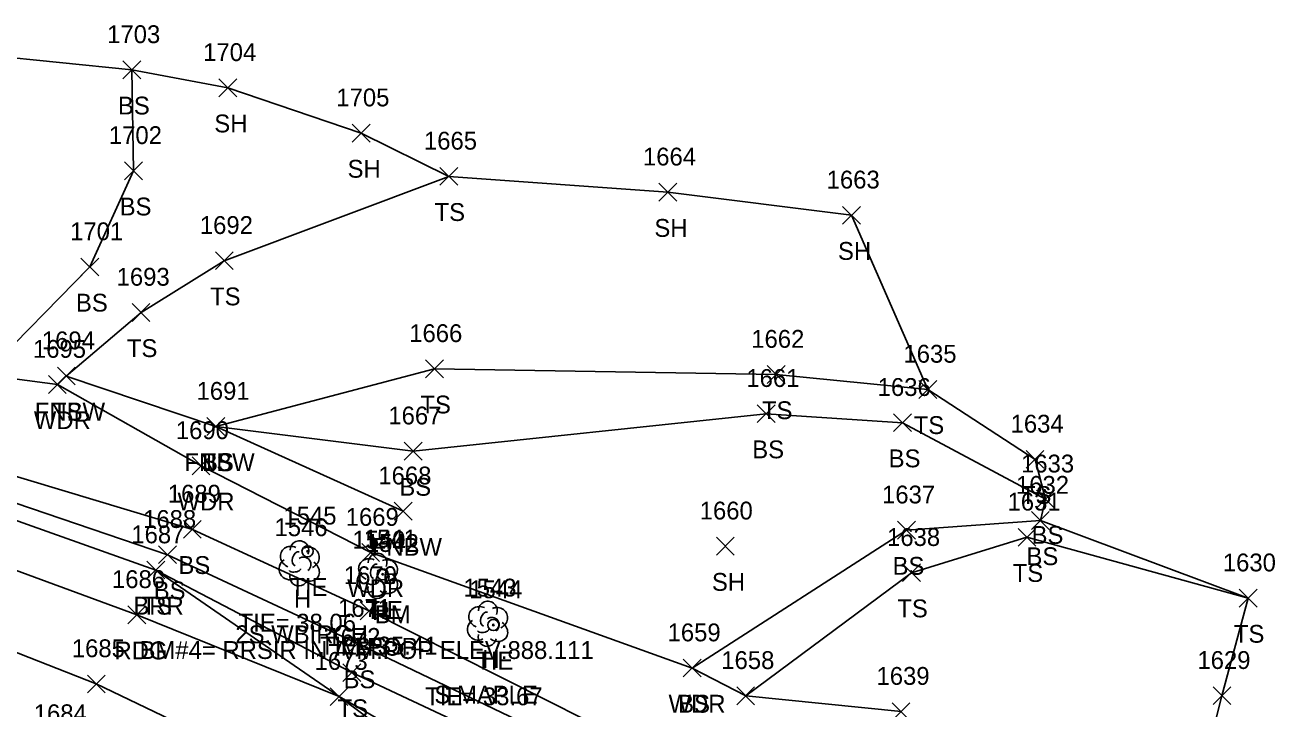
# Model space of a CAD drawing. Extents: x 1600281 to 1602254, y 862855 to 863227.
# Drawn here: x 1602113.6 to 1602253.7, y 863101.9 to 863178.4 of the extents above; entities that cross this region are included whole.
import ezdxf

# ---------------------------------------------------------------- set-up
doc = ezdxf.new("R2010")
doc.units = 0
for name, color, linetype in [('C_A', 7, 'Continuous'), ('C_C', 7, 'Continuous'), ('C_I', 7, 'Continuous'), ('CBP', 7, 'Continuous'), ('CPBM', 7, 'Continuous'), ('L_A', 7, 'Continuous'), ('L_C', 7, 'Continuous'), ('L_I', 7, 'Continuous'), ('L_TIC', 7, 'Continuous'), ('LABL', 7, 'Continuous'), ('LAWA', 7, 'Continuous'), ('LELB', 7, 'Continuous'), ('LFNC', 7, 'Continuous'), ('LSOGP', 7, 'Continuous'), ('LTD', 7, 'Continuous'), ('P_A', 7, 'Continuous'), ('P_I', 7, 'Continuous'), ('P_TIC', 7, 'Continuous'), ('PEU', 7, 'Continuous'), ('PRC', 7, 'Continuous')]:
    doc.layers.add(name, color=color, linetype=linetype)

msp = doc.modelspace()

# ---------------------------------------------------------------- linework, layer by layer
at = {"layer": 'CBP'}
for centre, radius in [((1602145.23, 863119.42), 0.625), ((1602145.23, 863119.42), 0.0833), ((1602153.66, 863116.85), 0.625), ((1602153.66, 863116.85), 0.0833), ((1602166.06, 863111.16), 0.625), ((1602166.06, 863111.16), 0.0833)]:
    msp.add_circle(centre, radius, dxfattribs=at)
at = {"layer": 'CPBM'}
for p, q in [((1602153.95, 863115.85), (1602153.95, 863116.85)), ((1602153.95, 863116.85), (1602154.95, 863116.85)), ((1602154.95, 863115.85), (1602153.95, 863115.85)), ((1602154.45, 863116.35), (1602154.45, 863116.35)), ((1602154.45, 863116.35), (1602154.45, 863116.35)), ((1602154.95, 863116.85), (1602154.95, 863115.85))]:
    msp.add_line(p, q, dxfattribs=at)
at = {"layer": 'L_TIC'}
for points in [[(1602124.54, 863172.4), (1602126.54, 863174.4)], [(1602126.54, 863172.4), (1602124.54, 863174.4)], [(1602135.3, 863170.39), (1602137.3, 863172.39)], [(1602137.3, 863170.39), (1602135.3, 863172.39)], [(1602150.24, 863165.31), (1602152.24, 863167.31)], [(1602152.24, 863165.31), (1602150.24, 863167.31)], [(1602124.73, 863161.08), (1602126.73, 863163.08)], [(1602126.73, 863161.08), (1602124.73, 863163.08)], [(1602160.07, 863160.46), (1602162.07, 863162.46)], [(1602162.07, 863160.46), (1602160.07, 863162.46)], [(1602184.62, 863158.68), (1602186.62, 863160.68)], [(1602186.62, 863158.68), (1602184.62, 863160.68)], [(1602205.21, 863156.1), (1602207.21, 863158.1)], [(1602207.21, 863156.1), (1602205.21, 863158.1)], [(1602119.83, 863150.3), (1602121.83, 863152.3)], [(1602121.83, 863150.3), (1602119.83, 863152.3)], [(1602134.9, 863151), (1602136.9, 863153)], [(1602136.9, 863151), (1602134.9, 863153)], [(1602125.57, 863145.2), (1602127.57, 863147.2)], [(1602127.57, 863145.2), (1602125.57, 863147.2)], [(1602158.47, 863138.88), (1602160.47, 863140.88)], [(1602160.47, 863138.88), (1602158.47, 863140.88)], [(1602117.19, 863138.07), (1602119.19, 863140.07)], [(1602119.19, 863138.07), (1602117.19, 863140.07)], [(1602117.19, 863138.07), (1602119.19, 863140.07)], [(1602119.19, 863138.07), (1602117.19, 863140.07)], [(1602196.76, 863138.24), (1602198.76, 863140.24)], [(1602198.76, 863138.24), (1602196.76, 863140.24)], [(1602116.19, 863137.12), (1602118.19, 863139.12)], [(1602118.19, 863137.12), (1602116.19, 863139.12)], [(1602213.77, 863136.57), (1602215.77, 863138.57)], [(1602215.77, 863136.57), (1602213.77, 863138.57)], [(1602195.64, 863133.85), (1602197.64, 863135.85)], [(1602197.64, 863133.85), (1602195.64, 863135.85)], [(1602133.96, 863132.41), (1602135.96, 863134.41)], [(1602135.96, 863132.41), (1602133.96, 863134.41)], [(1602133.96, 863132.41), (1602135.96, 863134.41)], [(1602135.96, 863132.41), (1602133.96, 863134.41)], [(1602133.96, 863132.41), (1602135.96, 863134.41)], [(1602135.96, 863132.41), (1602133.96, 863134.41)], [(1602210.93, 863132.84), (1602212.93, 863134.84)], [(1602212.93, 863132.84), (1602210.93, 863134.84)], [(1602156.07, 863129.65), (1602158.07, 863131.65)], [(1602158.07, 863129.65), (1602156.07, 863131.65)], [(1602132.29, 863128), (1602134.29, 863130)], [(1602134.29, 863128), (1602132.29, 863130)], [(1602225.78, 863128.73), (1602227.78, 863130.73)], [(1602227.78, 863128.73), (1602225.78, 863130.73)], [(1602226.95, 863124.26), (1602228.95, 863126.26)], [(1602228.95, 863124.26), (1602226.95, 863126.26)], [(1602154.96, 863122.92), (1602156.96, 863124.92)], [(1602156.96, 863122.92), (1602154.96, 863124.92)], [(1602131.32, 863120.88), (1602133.32, 863122.88)], [(1602133.32, 863120.88), (1602131.32, 863122.88)], [(1602211.37, 863120.79), (1602213.37, 863122.79)], [(1602213.37, 863120.79), (1602211.37, 863122.79)], [(1602226.38, 863121.87), (1602228.38, 863123.87)], [(1602228.38, 863121.87), (1602226.38, 863123.87)], [(1602224.87, 863119.99), (1602226.87, 863121.99)], [(1602226.87, 863119.99), (1602224.87, 863121.99)], [(1602128.54, 863118.04), (1602130.54, 863120.04)], [(1602130.54, 863118.04), (1602128.54, 863120.04)], [(1602151.31, 863118.28), (1602153.31, 863120.28)], [(1602153.31, 863118.28), (1602151.31, 863120.28)], [(1602191.07, 863118.99), (1602193.07, 863120.99)], [(1602193.07, 863118.99), (1602191.07, 863120.99)], [(1602127.22, 863116.32), (1602129.22, 863118.32)], [(1602129.22, 863116.32), (1602127.22, 863118.32)], [(1602127.22, 863116.32), (1602129.22, 863118.32)], [(1602129.22, 863116.32), (1602127.22, 863118.32)], [(1602211.93, 863116.02), (1602213.93, 863118.02)], [(1602213.93, 863116.02), (1602211.93, 863118.02)], [(1602249.66, 863113.17), (1602251.66, 863115.17)], [(1602251.66, 863113.17), (1602249.66, 863115.17)], [(1602151.13, 863111.74), (1602153.13, 863113.74)], [(1602153.13, 863111.74), (1602151.13, 863113.74)], [(1602149.82, 863108.07), (1602151.82, 863110.07)], [(1602151.82, 863108.07), (1602149.82, 863110.07)], [(1602187.34, 863105.33), (1602189.34, 863107.33)], [(1602189.34, 863105.33), (1602187.34, 863107.33)], [(1602187.34, 863105.33), (1602189.34, 863107.33)], [(1602189.34, 863105.33), (1602187.34, 863107.33)], [(1602149.19, 863104.82), (1602151.19, 863106.82)], [(1602151.19, 863104.82), (1602149.19, 863106.82)], [(1602147.76, 863102.13), (1602149.76, 863104.13)], [(1602149.76, 863102.13), (1602147.76, 863104.13)], [(1602193.35, 863102.22), (1602195.35, 863104.22)], [(1602195.35, 863102.22), (1602193.35, 863104.22)], [(1602193.35, 863102.22), (1602195.35, 863104.22)], [(1602195.35, 863102.22), (1602193.35, 863104.22)], [(1602246.73, 863102.23), (1602248.73, 863104.23)], [(1602248.73, 863102.23), (1602246.73, 863104.23)], [(1602210.76, 863100.45), (1602212.76, 863102.45)], [(1602212.76, 863100.45), (1602210.76, 863102.45)]]:
    msp.add_lwpolyline(points, dxfattribs=at)
at = {"layer": 'LABL'}
msp.add_lwpolyline([(1602238.45, 863059.38), (1602199.34, 863071.62), (1602179.65, 863080.08), (1602148.76, 863103.13), (1602128.22, 863117.32), (1602101.61, 863126.76), (1602102.3, 863128.31), (1602102.99, 863130.69), (1602105.29, 863133.38), (1602108.93, 863139.2)], dxfattribs=at)
at = {"layer": 'LAWA'}
msp.add_lwpolyline([(1602211.76, 863101.45), (1602194.35, 863103.22), (1602188.34, 863106.33), (1602152.31, 863119.28), (1602133.29, 863129), (1602117.19, 863138.12), (1602108.93, 863139.2)], dxfattribs=at)
at = {"layer": 'LELB'}
for points in [[(1602108.93, 863139.2), (1602120.83, 863151.3), (1602125.73, 863162.08), (1602125.54, 863173.4)], [(1602161.07, 863161.46), (1602135.9, 863152), (1602126.57, 863146.2), (1602118.19, 863139.07)], [(1602226.78, 863129.73), (1602214.77, 863137.57), (1602197.76, 863139.24), (1602159.47, 863139.88), (1602134.96, 863133.41)], [(1602227.95, 863125.26), (1602211.93, 863133.84), (1602196.64, 863134.85), (1602157.07, 863130.65), (1602134.96, 863133.41)], [(1602242.08, 863077.12), (1602206.81, 863090.25), (1602186.39, 863095.47), (1602152.13, 863112.74), (1602132.32, 863121.88), (1602102.99, 863130.69), (1602094.92, 863127.7), (1602081.09, 863125.32), (1602069.71, 863119.92), (1602067.84, 863117.44), (1602062.23, 863111.77), (1602054.78, 863103.53)], [(1602241.55, 863072.3), (1602203.83, 863084.04), (1602184.9, 863092.77), (1602150.82, 863109.07), (1602129.54, 863119.04), (1602102.3, 863128.31), (1602095.85, 863125.02), (1602082.9, 863122.06), (1602071.56, 863117.44), (1602069.71, 863115.85), (1602064.38, 863110.75), (1602060.62, 863098.3)], [(1602227.38, 863122.87), (1602212.37, 863121.79), (1602188.34, 863106.33)], [(1602250.66, 863114.17), (1602225.87, 863120.99), (1602212.93, 863117.02), (1602194.35, 863103.22)], [(1602240.62, 863068.77), (1602202.94, 863080.55), (1602183.74, 863090.05), (1602150.19, 863105.82), (1602128.22, 863117.32)]]:
    msp.add_lwpolyline(points, dxfattribs=at)
at = {"layer": 'LFNC'}
msp.add_lwpolyline([(1602155.96, 863123.92), (1602134.96, 863133.41), (1602118.19, 863139.07)], dxfattribs=at)
at = {"layer": 'LSOGP'}
msp.add_lwpolyline([(1602244.26, 863089.39), (1602247.73, 863103.23), (1602250.66, 863114.17), (1602227.38, 863122.87), (1602227.95, 863125.26), (1602226.78, 863129.73), (1602214.77, 863137.57), (1602206.21, 863157.1), (1602185.62, 863159.68), (1602161.07, 863161.46), (1602151.24, 863166.31), (1602136.3, 863171.39), (1602125.54, 863173.4), (1602109.27, 863175.06)], dxfattribs=at)
at = {"layer": 'LTD'}
for p, q in [((1602144.28, 863118.12), (1602144.28, 863118.12)), ((1602144.28, 863118.12), (1602144.28, 863118.12)), ((1602153.04, 863116.72), (1602153.04, 863116.72)), ((1602153.04, 863116.72), (1602153.04, 863116.72)), ((1602165.39, 863111.35), (1602165.39, 863111.35)), ((1602165.39, 863111.35), (1602165.39, 863111.35))]:
    msp.add_line(p, q, dxfattribs=at)
for centre in [(1602144.32, 863119.55), (1602153.08, 863118.15), (1602165.44, 863112.78)]:
    msp.add_arc(centre, 1.05, 335.5272, 180.9563, dxfattribs=at)
for centre, major_axis, ratio, start_param, end_param in [((1602143.48, 863118.78), (1.21, -0.51), 0.895232, 1.570796, 4.712389), ((1602145.32, 863118.7), (-1.14, -0.48), 0.949671, 1.570796, 4.712389), ((1602143.19, 863117.41), (0.58, -1.04), 0.959034, 3.141593, 6.283185), ((1602144.07, 863118.57), (-0.208, -0.792), 0.645439, 3.141593, 6.283185), ((1602144.78, 863117.95), (-0.5, 0.667), 0.989748, 3.141593, 6.283185), ((1602152.25, 863117.39), (1.21, -0.51), 0.895232, 1.570796, 4.712389), ((1602154.08, 863117.3), (-1.14, -0.48), 0.949671, 1.570796, 4.712389), ((1602143.82, 863117.37), (-0.625, -0.083), 0.423636, 0, 3.141593), ((1602145.28, 863117.28), (-1.09, 0.79), 0.841452, 1.570796, 4.712389), ((1602151.95, 863116.01), (0.58, -1.04), 0.959034, 3.141593, 6.283185), ((1602152.83, 863117.18), (-0.208, -0.792), 0.645439, 3.141593, 6.283185), ((1602153.54, 863116.55), (-0.5, 0.667), 0.989748, 3.141593, 6.283185), ((1602144.28, 863116.62), (0.26, 1.06), 0.942809, 1.570796, 4.712389), ((1602152.58, 863115.97), (-0.625, -0.083), 0.423636, 0, 3.141593), ((1602154.04, 863115.89), (-1.09, 0.79), 0.841452, 1.570796, 4.712389), ((1602153.04, 863115.22), (0.26, 1.06), 0.942809, 1.570796, 4.712389), ((1602164.6, 863112.02), (1.21, -0.51), 0.895232, 1.570796, 4.712389), ((1602166.43, 863111.93), (-1.14, -0.48), 0.949671, 1.570796, 4.712389), ((1602164.31, 863110.64), (0.58, -1.04), 0.959034, 3.141593, 6.283185), ((1602165.18, 863111.81), (-0.208, -0.792), 0.645439, 3.141593, 6.283185), ((1602165.89, 863111.18), (-0.5, 0.667), 0.989748, 3.141593, 6.283185), ((1602166.39, 863110.52), (-1.09, 0.79), 0.841452, 1.570796, 4.712389), ((1602165.39, 863109.85), (0.26, 1.06), 0.942809, 1.570796, 4.712389), ((1602164.93, 863110.6), (-0.625, -0.083), 0.423636, 0, 3.141593)]:
    msp.add_ellipse(centre, major_axis=major_axis, ratio=ratio, start_param=start_param, end_param=end_param, dxfattribs=at)
at = {"layer": 'P_TIC'}
for points in [[(1602125.1, 863111.3), (1602127.1, 863113.3)], [(1602127.1, 863111.3), (1602125.1, 863113.3)], [(1602120.55, 863103.55), (1602122.55, 863105.55)], [(1602122.55, 863103.55), (1602120.55, 863105.55)], [(1602147.76, 863102.13), (1602149.76, 863104.13)], [(1602149.76, 863102.13), (1602147.76, 863104.13)]]:
    msp.add_lwpolyline(points, dxfattribs=at)
at = {"layer": 'PEU'}
msp.add_lwpolyline([(1602239.32, 863063.19), (1602201.86, 863077.58), (1602181.73, 863084.14), (1602148.76, 863103.13), (1602126.1, 863112.3), (1602096.31, 863123.24), (1602085.65, 863117.24), (1602075.42, 863112.31), (1602066.28, 863103.64), (1602062.25, 863097.25), (1602069.56, 863092.76), (1602076.19, 863089.04)], dxfattribs=at)
at = {"layer": 'PRC'}
msp.add_lwpolyline([(1602236.4, 863054.64), (1602198.66, 863067.23), (1602177.31, 863075.3), (1602143.81, 863093.88), (1602121.55, 863104.55), (1602098.78, 863113.5), (1602079.15, 863104.73), (1602069.56, 863092.76)], dxfattribs=at)

# ---------------------------------------------------------------- texts
at = {"layer": 'C_A'}
for s, p in [('TIE', (1602143.31, 863114.42)), ('TIE', (1602151.74, 863111.85)), ('BM', (1602152.77, 863111.35)), ('TIE', (1602164.14, 863106.16))]:
    msp.add_text(s, height=2, dxfattribs=at).set_placement(p)
at = {"layer": 'C_C'}
for s, p in [('TIE= 38.06', (1602137.5, 863110.42)), ('BM#4= RRSIR IN A M.POP ELEV:888.111', (1602126.4, 863107.35)), ('TIE= 35.41', (1602146.63, 863107.85)), ('TIE= 33.67', (1602158.42, 863102.16))]:
    msp.add_text(s, height=2, dxfattribs=at).set_placement(p)
at = {"layer": 'C_I'}
for s, p in [('1545', (1602142.53, 863122.42)), ('1541', (1602151.53, 863119.85)), ('1542', (1602151.76, 863119.35)), ('1544', (1602163.36, 863114.16))]:
    msp.add_text(s, height=2, dxfattribs=at).set_placement(p)
at = {"layer": 'L_A'}
for s, p in [('BS', (1602123.98, 863168.4)), ('SH', (1602134.78, 863166.39)), ('SH', (1602149.72, 863161.31)), ('BS', (1602124.17, 863157.08)), ('TS', (1602159.47, 863156.46)), ('SH', (1602184.11, 863154.68)), ('SH', (1602204.69, 863152.1)), ('BS', (1602119.27, 863146.3)), ('TS', (1602134.31, 863147)), ('TS', (1602124.98, 863141.2)), ('TS', (1602157.88, 863134.88)), ('FNBW', (1602114.66, 863134.07)), ('TS', (1602116.6, 863134.07)), ('TS', (1602196.17, 863134.24)), ('WDR', (1602114.55, 863133.12)), ('TS', (1602213.18, 863132.57)), ('BS', (1602195.08, 863129.85)), ('FNBW', (1602131.43, 863128.41)), ('TS', (1602133.37, 863128.41)), ('BS', (1602133.4, 863128.41)), ('BS', (1602210.37, 863128.84)), ('BS', (1602155.52, 863125.65)), ('WDR', (1602130.66, 863124)), ('TS', (1602225.19, 863124.73)), ('BS', (1602226.39, 863120.26)), ('FNBW', (1602152.43, 863118.92)), ('BS', (1602225.82, 863117.87)), ('BS', (1602130.76, 863116.88)), ('BS', (1602210.81, 863116.79)), ('SH', (1602190.56, 863114.99)), ('TS', (1602224.28, 863115.99)), ('BS', (1602127.99, 863114.04)), ('WDR', (1602149.67, 863114.28)), ('BRR', (1602125.71, 863112.32)), ('TS', (1602126.63, 863112.32)), ('H', (1602143.71, 863113.12)), ('H', (1602152.47, 863111.72)), ('TS', (1602211.34, 863112.02)), ('TS', (1602249.07, 863109.17)), ('BS', (1602150.57, 863107.74)), ('H', (1602164.82, 863106.35)), ('BS', (1602149.27, 863104.07)), ('WDR', (1602185.7, 863101.33)), ('BS', (1602186.78, 863101.33)), ('TS', (1602148.6, 863100.82))]:
    msp.add_text(s, height=2, dxfattribs=at).set_placement(p)
at = {"layer": 'L_C'}
for s, p in [('2S.WBIRCH', (1602137.14, 863109.12)), ('M.POP', (1602148.94, 863107.72)), ('S.MAPLE', (1602159.45, 863102.35))]:
    msp.add_text(s, height=2, dxfattribs=at).set_placement(p)
at = {"layer": 'L_I'}
for s, p in [('1703', (1602122.77, 863176.4)), ('1704', (1602133.53, 863174.39)), ('1705', (1602148.46, 863169.31)), ('1702', (1602122.96, 863165.08)), ('1665', (1602158.28, 863164.46)), ('1664', (1602182.83, 863162.68)), ('1663', (1602203.42, 863160.1)), ('1701', (1602118.62, 863154.3)), ('1692', (1602133.16, 863155)), ('1693', (1602123.83, 863149.2)), ('1694', (1602115.45, 863142.07)), ('1694', (1602115.45, 863142.07)), ('1666', (1602156.63, 863142.88)), ('1662', (1602194.97, 863142.24)), ('1695', (1602114.45, 863141.12)), ('1635', (1602212.03, 863140.57)), ('1661', (1602194.42, 863137.85)), ('1691', (1602132.79, 863136.41)), ('1691', (1602132.79, 863136.41)), ('1691', (1602132.79, 863136.41)), ('1636', (1602209.14, 863136.84)), ('1667', (1602154.29, 863133.65)), ('1690', (1602130.47, 863132)), ('1634', (1602224.04, 863132.73)), ('1633', (1602225.21, 863128.26)), ('1668', (1602153.17, 863126.92)), ('1689', (1602129.57, 863124.88)), ('1637', (1602209.63, 863124.79)), ('1632', (1602224.64, 863125.87)), ('1631', (1602223.7, 863123.99)), ('1688', (1602126.8, 863122.04)), ('1669', (1602149.51, 863122.28)), ('1660', (1602189.19, 863122.99)), ('1546', (1602141.53, 863121.12)), ('1687', (1602125.48, 863120.32)), ('1687', (1602125.48, 863120.32)), ('1540', (1602150.26, 863119.72)), ('1638', (1602210.19, 863120.02)), ('1630', (1602247.83, 863117.17)), ('1670', (1602149.3, 863115.74)), ('1543', (1602162.7, 863114.35)), ('1671', (1602148.65, 863112.07)), ('1659', (1602185.59, 863109.33)), ('1659', (1602185.59, 863109.33)), ('1672', (1602147.45, 863108.82)), ('1673', (1602146.02, 863106.13)), ('1658', (1602191.61, 863106.22)), ('1658', (1602191.61, 863106.22)), ('1629', (1602244.98, 863106.23)), ('1639', (1602209.01, 863104.45))]:
    msp.add_text(s, height=2, dxfattribs=at).set_placement(p)
at = {"layer": 'P_A'}
msp.add_text('RDG', height=2, dxfattribs=at).set_placement((1602123.59, 863107.3))
at = {"layer": 'P_I'}
for s, p in [('1686', (1602123.31, 863115.3)), ('1685', (1602118.81, 863107.55)), ('1673', (1602146.02, 863106.13)), ('1684', (1602114.54, 863100.26))]:
    msp.add_text(s, height=2, dxfattribs=at).set_placement(p)

doc.saveas('drawing.dxf')
